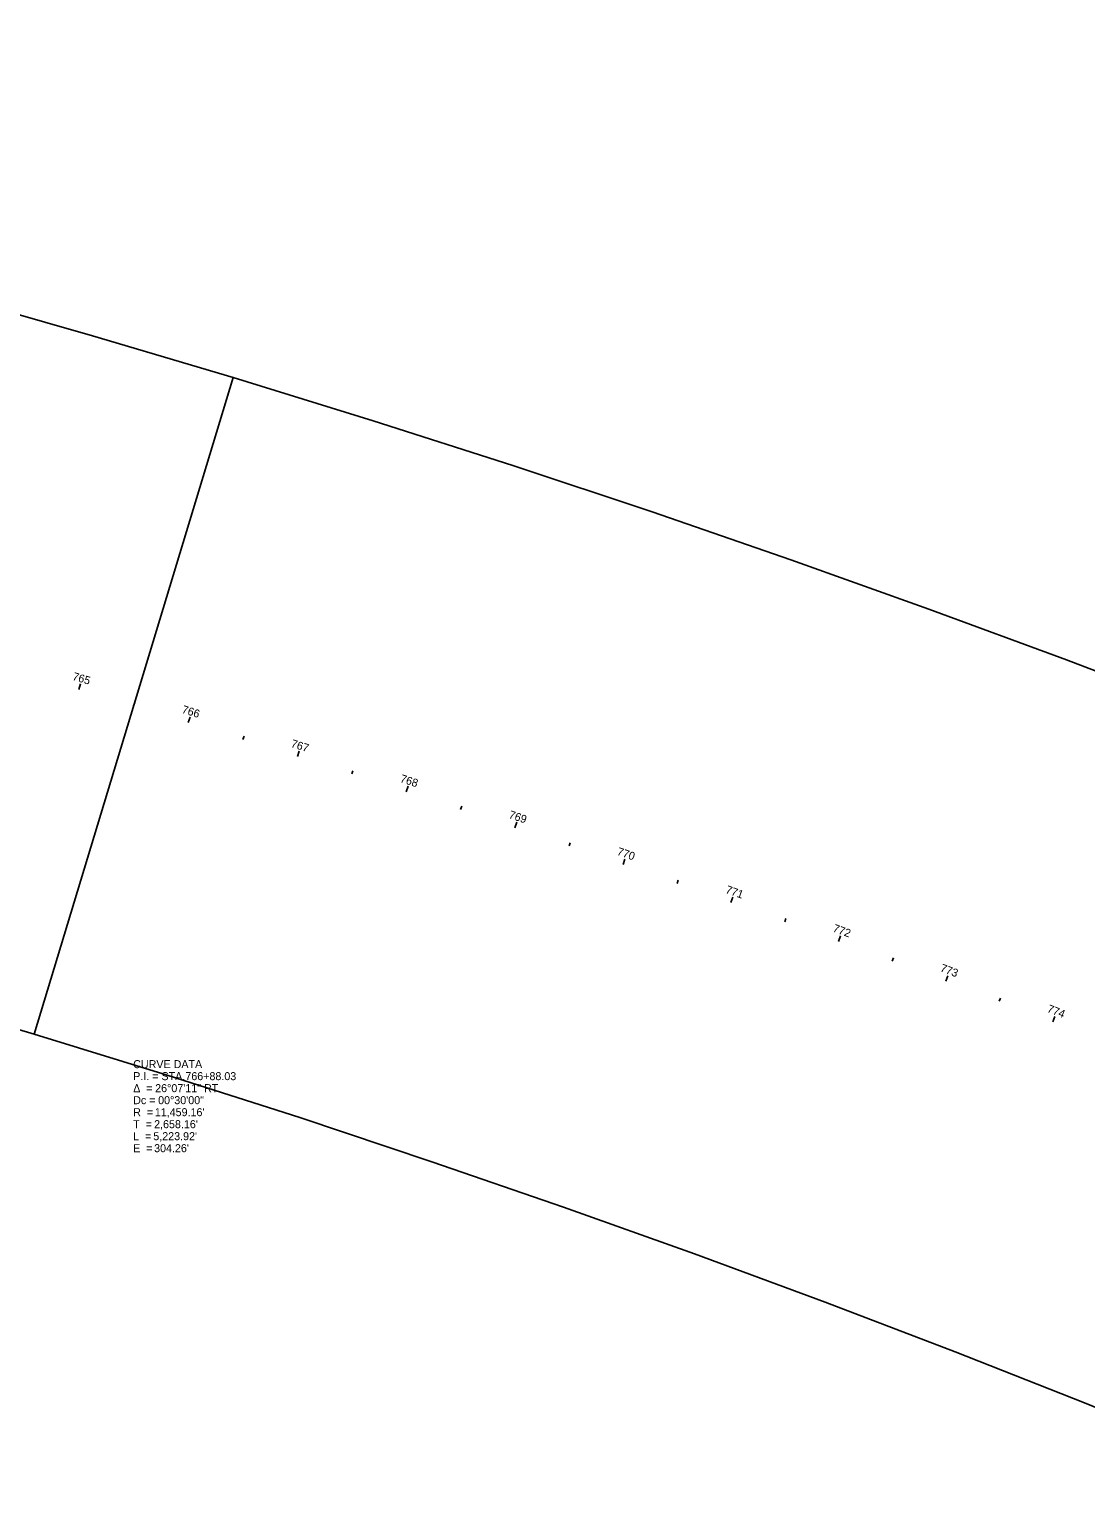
# Model space of a CAD drawing. Extents: x 75725 to 90554, y 518585 to 527848.
# Drawn here: x 79356 to 80279, y 526295 to 527589 of the extents above; entities that cross this region are included whole.
import ezdxf

# ---------------------------------------------------------------- set-up
doc = ezdxf.new("R2010")
doc.units = 0
for name, color, linetype in [('GE_P_Alignment_100_Curve_Data', 7, 'Continuous'), ('GE_P_Alignment_100_Stations', 7, 'Continuous'), ('SH_Named_Boundary', 7, 'Continuous')]:
    doc.layers.add(name, color=color, linetype=linetype)

msp = doc.modelspace()

# ---------------------------------------------------------------- linework, layer by layer
at = {"layer": 'GE_P_Alignment_100_Stations'}
for p, q in [((79398.7, 527011.9), (79400.1, 527016.7)), ((79446.6, 526997.5), (79447.5, 527000.4)), ((79494.4, 526982.9), (79495.9, 526987.7)), ((79542.2, 526968.1), (79543.1, 526971)), ((79589.9, 526953.1), (79591.4, 526957.9)), ((79637.5, 526937.9), (79638.4, 526940.7)), ((79685, 526922.4), (79686.6, 526927.2)), ((79732.5, 526906.8), (79733.5, 526909.6)), ((79780, 526890.9), (79781.6, 526895.7)), ((79827.3, 526874.9), (79828.3, 526877.7)), ((79874.6, 526858.6), (79876.2, 526863.4)), ((79921.8, 526842.2), (79922.8, 526845)), ((79968.9, 526825.5), (79970.6, 526830.2)), ((80016, 526808.6), (80017, 526811.4)), ((80063, 526791.5), (80064.7, 526796.2)), ((80109.9, 526774.2), (80111, 526777.1)), ((80156.8, 526756.7), (80158.5, 526761.4)), ((80203.5, 526739.1), (80204.6, 526741.9)), ((80250.2, 526721.2), (80252, 526725.8))]:
    msp.add_line(p, q, dxfattribs=at)
at = {"layer": 'SH_Named_Boundary'}
for points in [[(78288.1, 527588.9), (78177.7, 526999.1), (78297.2, 526976.1), (78416.5, 526951.7), (78535.5, 526926.1), (78654.2, 526899.1), (78772.6, 526870.9), (78890.7, 526841.3), (79008.5, 526810.5), (79125.9, 526778.4), (79242.9, 526745), (79359.6, 526710.4), (79533.6, 527284.6), (79410.6, 527321.1), (79287.3, 527356.3), (79163.5, 527390.1), (79039.4, 527422.6), (78915, 527453.7), (78790.2, 527483.5), (78665.1, 527511.9), (78539.7, 527538.9), (78414.1, 527564.6)], [(79533.6, 527284.6), (79359.6, 526710.4), (79475.9, 526674.5), (79591.8, 526637.3), (79707.3, 526598.8), (79822.4, 526559.1), (79937, 526518.1), (80051.2, 526475.9), (80164.9, 526432.5), (80278.1, 526387.8), (80390.9, 526341.9), (80503.1, 526294.7), (80738.5, 526846.6), (80620.3, 526896.3), (80501.5, 526944.7), (80382.2, 526991.8), (80262.3, 527037.6), (80142, 527082), (80021.2, 527125.2), (79900, 527167.1), (79778.3, 527207.6), (79656.1, 527246.8)]]:
    msp.add_lwpolyline(points, close=True, dxfattribs=at)

# ---------------------------------------------------------------- texts
at = {"layer": 'GE_P_Alignment_100_Curve_Data'}
for s, p in [('CURVE DATA', (79446.2, 526680.6)), ('P.I. = STA. ', (79446.2, 526670.1)), ('766+88.03', (79491.8, 526670.1)), ('Δ  = ', (79446.2, 526659.6)), ('26°07\'11" RT', (79465.4, 526659.6)), ('Dc = ', (79446.2, 526649.1)), ('00°30\'00"', (79468, 526649.1)), ('R  = ', (79446.2, 526638.6)), ("11,459.16'", (79465.1, 526638.6)), ('T  = ', (79446.2, 526628.1)), ("2,658.16'", (79464.5, 526628.1)), ('L  = ', (79446.2, 526617.6)), ('E  = ', (79446.2, 526607.1)), ("5,223.92'", (79463.8, 526617.6)), ("304.26'", (79464.5, 526607.1))]:
    msp.add_text(s, height=7, dxfattribs=at).set_placement(p)
at = {"layer": 'GE_P_Alignment_100_Stations'}
for s, rotation, p in [('765', 343.3972, (79392.6, 527020.3)), ('766', 342.8972, (79488.2, 526991.4)), ('767', 342.3972, (79583.6, 526961.6)), ('768', 341.8972, (79679.1, 526931)), ('769', 341.3972, (79774.1, 526899.5)), ('770', 340.8972, (79868.7, 526867.3)), ('771', 340.3972, (79963.6, 526834)), ('772', 339.8972, (80057.4, 526800.2)), ('773', 339.3972, (80151.3, 526765.5)), ('774', 338.8972, (80244.8, 526729.9))]:
    msp.add_text(s, height=7, rotation=rotation, dxfattribs=at).set_placement(p)

doc.saveas('drawing.dxf')
